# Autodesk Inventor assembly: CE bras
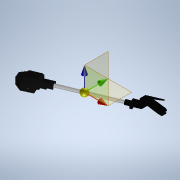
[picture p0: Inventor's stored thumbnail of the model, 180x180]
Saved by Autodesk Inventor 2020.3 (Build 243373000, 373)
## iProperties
Created: 2020-09
Part Number: CE bras
Document SubType Name: Assembly
Designer: ficho
Mass: 26.5419 g
Surface Area: 163.757 cm^2
Volume: 9.2774 cm^3
Density: 2.86092 g/cm^3
Author: ficho
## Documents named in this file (5)
- G:\travail\année 2020-2021\2I2D\platine disque\platine 3D\CE bras.iam
- G:\travail\année 2020-2021\2I2D\platine disque\platine 3D\contre poids bras.ipt
- G:\travail\année 2020-2021\2I2D\platine disque\platine 3D\tête bras.ipt
- G:\travail\année 2020-2021\2I2D\platine disque\platine 3D\tube bras.ipt
- G:\travail\année 2020-2021\2I2D\platine disque\platine 3D\axe.ipt
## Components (4 placed, 4 different names)
1. contre poids bras:1 — Logement:1, Affleurement:1
2. tête bras:1 — Logement:2
3. tube bras:1 — Logement:1, Logement:2
4. axe:1 — Affleurement:1
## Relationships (3: Insert 2, Flush 1)
- Logement:1 [Insert]: contre poids bras:1 ↔ tube bras:1
- Logement:2 [Insert]: tête bras:1 ↔ tube bras:1
- Affleurement:1 [Flush]: contre poids bras:1 ↔ axe:1
